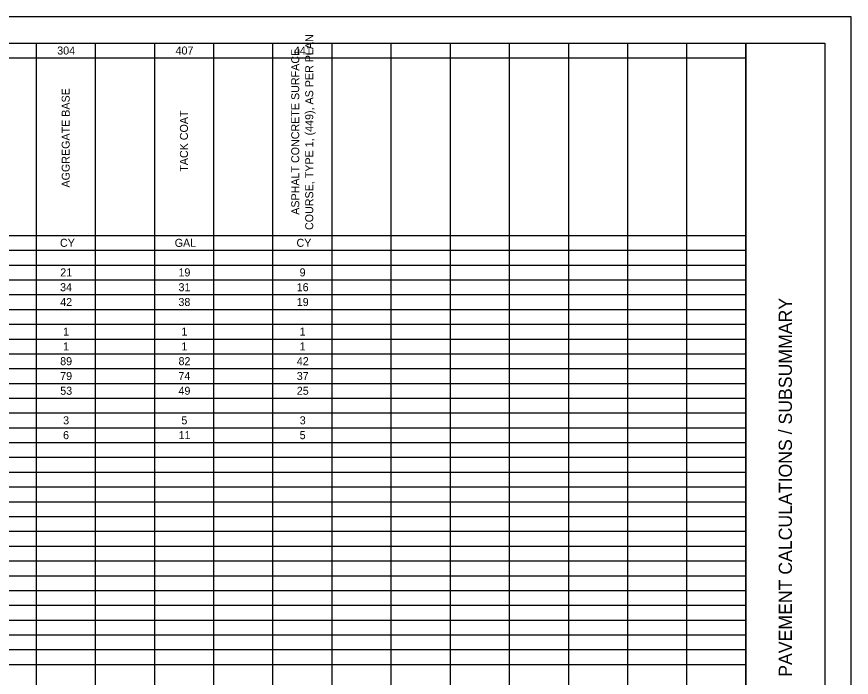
# Model space of a CAD drawing. Extents: x -43.4 to 36.7, y 0 to 22.
# Drawn here: x 18.07 to 33.88, y 9.47 to 21.98 of the extents above; entities that cross this region are included whole.
import ezdxf

# ---------------------------------------------------------------- set-up
doc = ezdxf.new("R2010")
doc.units = 0
for name, color, linetype in [('SH_Border', 7, 'Continuous'), ('SH_Cut_Line', 7, 'Continuous'), ('SH_Data', 7, 'Continuous'), ('SH_Text', 7, 'Continuous')]:
    doc.layers.add(name, color=color, linetype=linetype)

msp = doc.modelspace()

# ---------------------------------------------------------------- linework, layer by layer
at = {"layer": 'SH_Border'}
msp.add_line((31.876, 0.475), (31.876, 21.475), dxfattribs=at)
msp.add_lwpolyline([(1.376, 21.475), (33.376, 21.475), (33.376, 0.475), (1.376, 0.475)], close=True, dxfattribs=at)
at = {"layer": 'SH_Cut_Line'}
msp.add_lwpolyline([(-0.124, -0.025), (33.876, -0.025), (33.876, 21.975), (-0.124, 21.975)], close=True, dxfattribs=at)
at = {"layer": 'SH_Data'}
for p, q in [((1.376, 21.475), (31.877, 21.475)), ((18.438, 21.475), (18.438, 0.477)), ((19.558, 21.475), (19.558, 0.477)), ((20.678, 21.475), (20.678, 0.477)), ((21.798, 21.475), (21.798, 0.477)), ((22.917, 21.475), (22.917, 0.477)), ((24.037, 21.475), (24.037, 0.477)), ((25.157, 21.475), (25.157, 0.477)), ((26.277, 21.475), (26.277, 0.477)), ((27.397, 21.475), (27.397, 0.477)), ((28.517, 21.475), (28.517, 0.477)), ((29.637, 21.475), (29.637, 0.477)), ((30.757, 21.475), (30.757, 0.477)), ((31.877, 21.475), (31.877, 0.477)), ((11.718, 21.195), (31.877, 21.195)), ((7.239, 17.835), (31.877, 17.835)), ((1.376, 17.555), (31.877, 17.555)), ((1.376, 17.275), (31.877, 17.275)), ((1.376, 16.995), (31.877, 16.995)), ((1.376, 16.715), (31.877, 16.715)), ((1.376, 16.435), (31.877, 16.435)), ((1.376, 16.155), (31.877, 16.155)), ((1.376, 15.875), (31.877, 15.875)), ((1.376, 15.596), (31.877, 15.596)), ((1.376, 15.316), (31.877, 15.316)), ((1.376, 15.036), (31.877, 15.036)), ((1.376, 14.756), (31.877, 14.756)), ((1.376, 14.476), (31.877, 14.476)), ((1.376, 14.196), (31.877, 14.196)), ((1.376, 13.916), (31.877, 13.916)), ((1.376, 13.636), (31.877, 13.636)), ((1.376, 13.356), (31.877, 13.356)), ((1.376, 13.076), (31.877, 13.076)), ((1.376, 12.796), (31.877, 12.796)), ((1.376, 12.516), (31.877, 12.516)), ((1.376, 12.236), (31.877, 12.236)), ((1.376, 11.956), (31.877, 11.956)), ((1.376, 11.676), (31.877, 11.676)), ((1.376, 11.396), (31.877, 11.396)), ((1.376, 11.116), (31.877, 11.116)), ((1.376, 10.836), (31.877, 10.836)), ((1.376, 10.556), (31.877, 10.556)), ((1.376, 10.276), (31.877, 10.276)), ((1.376, 9.996), (31.877, 9.996)), ((1.376, 9.716), (31.877, 9.716))]:
    msp.add_line(p, q, dxfattribs=at)

# ---------------------------------------------------------------- texts
msp.add_text('PAVEMENT CALCULATIONS / SUBSUMMARY', height=0.25, rotation=90, dxfattribs=at).set_placement((32.751, 9.483))
at = {"layer": 'SH_Text'}
for s, height, p in [('COURSE, TYPE 1, (449), AS PER PLAN', 0.15152, (23.686, 17.938)), ('ASPHALT CONCRETE SURFACE ', 0.15152, (23.421, 18.226)), ('AGGREGATE BASE', 0.15152, (19.074, 18.742)), ('TACK COAT', 0.1515, (21.313, 19.041))]:
    msp.add_text(s, height=height, rotation=90, dxfattribs=at).set_placement(p)
for s, height, p in [('304', 0.1515, (18.838, 21.259)), ('407', 0.1515, (21.079, 21.259)), ('441', 0.1515, (23.32, 21.259)), ('CY', 0.1515, (18.89, 17.62)), ('GAL', 0.1515, (21.063, 17.62)), ('CY', 0.1515, (23.369, 17.62)), ('21', 0.1515, (18.895, 17.06)), ('19', 0.1515, (21.134, 17.06)), ('9', 0.152, (23.428, 17.06)), ('34', 0.1515, (18.892, 16.78)), ('31', 0.1515, (21.135, 16.78)), ('16', 0.1515, (23.373, 16.78)), ('42', 0.1515, (18.895, 16.5)), ('38', 0.1515, (21.133, 16.5)), ('19', 0.1515, (23.374, 16.5)), ('1', 0.152, (18.949, 15.94)), ('1', 0.152, (21.189, 15.94)), ('1', 0.152, (23.429, 15.94)), ('1', 0.152, (18.949, 15.66)), ('1', 0.152, (21.189, 15.66)), ('1', 0.152, (23.429, 15.66)), ('89', 0.1515, (18.894, 15.38)), ('82', 0.1515, (21.135, 15.38)), ('42', 0.1515, (23.375, 15.38)), ('79', 0.1515, (18.894, 15.1)), ('74', 0.1515, (21.132, 15.1)), ('37', 0.1515, (23.374, 15.1)), ('53', 0.1515, (18.895, 14.82)), ('49', 0.1515, (21.134, 14.82)), ('25', 0.1515, (23.375, 14.82)), ('3', 0.152, (18.95, 14.26)), ('5', 0.152, (21.189, 14.26)), ('3', 0.152, (23.43, 14.26)), ('6', 0.152, (18.948, 13.98)), ('11', 0.1515, (21.135, 13.98)), ('5', 0.152, (23.429, 13.98))]:
    msp.add_text(s, height=height, dxfattribs=at).set_placement(p)

doc.saveas('drawing.dxf')
